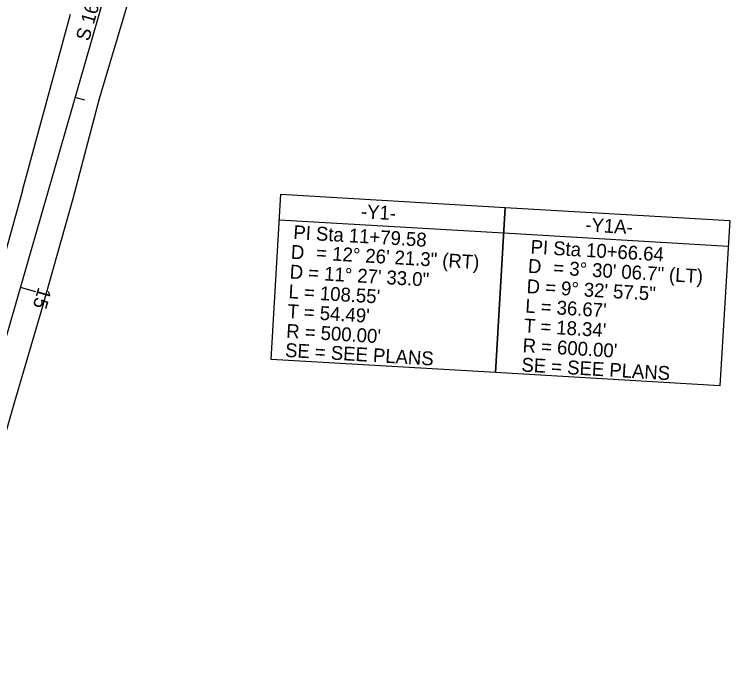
# Model space of a CAD drawing. Extents: x 2010838 to 2015151, y 441905 to 447792.
# Drawn here: x 2012294.2 to 2012655.8, y 444289.1 to 444614.7 of the extents above; entities that cross this region are included whole.
import ezdxf

# ---------------------------------------------------------------- set-up
doc = ezdxf.new("R2010")
doc.units = 0
for name, color, linetype in [('$AUDIT_BAD_LAYER1', 7, 'Continuous'), ('C-Building', 7, 'Continuous'), ('C-EOP 1', 7, 'Continuous'), ('CLRD', 7, 'Continuous'), ('Cont-2-Lidar', 7, 'Continuous'), ('Default_2FT_LIDAR_Contour', 7, 'Continuous'), ('Default_Parcels', 7, 'Continuous'), ('S-overhead electric', 7, 'Continuous')]:
    doc.layers.add(name, color=color, linetype=linetype)

msp = doc.modelspace()

# ---------------------------------------------------------------- linework, layer by layer
at = {"layer": '$AUDIT_BAD_LAYER1'}
msp.add_line((2012370.93, 444732.79), (2012193.35, 444115.92), dxfattribs=at)
at = {"layer": 'C-Building'}
msp.add_line((2012324.91, 444572.92), (2012329.71, 444571.54), dxfattribs=at)
at = {"layer": 'C-EOP 1'}
msp.add_line((2012297.24, 444476.83), (2012304.93, 444474.61), dxfattribs=at)
at = {"layer": 'CLRD'}
msp.add_line((2012370.93, 444732.79), (2012193.35, 444115.92), dxfattribs=at)
at = {"layer": 'Default_Parcels'}
for p, q in [((2012428.15, 444510.89), (2012541.6, 444504.21)), ((2012541.6, 444504.21), (2012655.05, 444497.52))]:
    msp.add_line(p, q, dxfattribs=at)
for points in [[(2012428.91, 444523.85), (2012542.37, 444517.16), (2012537.44, 444433.65), (2012423.99, 444440.34)], [(2012542.37, 444517.16), (2012655.82, 444510.48), (2012650.89, 444426.96), (2012537.44, 444433.65)]]:
    msp.add_lwpolyline(points, close=True, dxfattribs=at)
at = {"layer": 'S-overhead electric'}
msp.add_line((2012298.31, 444525.62), (2012322.65, 444614.7), dxfattribs=at)
for points in [[(2012214.85, 444140.57), (2012231.36, 444197.54), (2012246.95, 444252.5), (2012262.48, 444306.6), (2012277.82, 444361.05), (2012294.5, 444419.12), (2012308.07, 444465.48), (2012323.92, 444521.61), (2012337.25, 444572.21), (2012352.19, 444622.1), (2012368.35, 444674.41)], [(2012298.31, 444525.62), (2012284.21, 444475.17), (2012267.75, 444418.87), (2012251.33, 444361.5), (2012234.87, 444302.97), (2012222.75, 444260.78), (2012211.14, 444219.75), (2012193.27, 444158.36)]]:
    msp.add_lwpolyline(points, dxfattribs=at)
msp.add_ellipse((2012288.54, 444624.12), major_axis=(20.27, 29.02), ratio=0.999636, start_param=5.052702, end_param=5.052702, dxfattribs=at)

# ---------------------------------------------------------------- texts
at = {"layer": 'Cont-2-Lidar'}
msp.add_text('S 16%%d 03\' 35.1" W', height=7, rotation=73.9402, dxfattribs=at).set_placement((2012331.92, 444600.75))
at = {"layer": 'Default_2FT_LIDAR_Contour'}
msp.add_text('15', height=7, rotation=253.9402, dxfattribs=at).set_placement((2012306.41, 444477.11))
at = {"layer": 'Default_Parcels'}
for s, p in [('-Y1-', (2012469.28, 444511.69)), ('-Y1A-', (2012582.73, 444505)), ('PI Sta 11+79.58', (2012435.13, 444501.19)), ('D', (2012433.87, 444491.24)), ('PI Sta 10+66.64', (2012555.03, 444493.8)), ('= 12%%d 26\' 21.3" (RT)', (2012446.72, 444490.78)), ('D', (2012553.71, 444484.14)), ('D = 11%%d 27\' 33.0"', (2012433.28, 444481.26)), ('= 3%%d 30\' 06.7" (LT)', (2012566.53, 444483.25)), ('D = 9%%d 32\' 57.5"', (2012553.01, 444473.88)), ("L = 108.55'", (2012432.69, 444471.28)), ("L = 36.67'", (2012552.35, 444464.01)), ("T = 54.49'", (2012432.11, 444461.3)), ("R = 500.00'", (2012431.52, 444451.31)), ("T = 18.34'", (2012551.67, 444454.03)), ("R = 600.00'", (2012551, 444444.01)), ('SE = SEE PLANS', (2012430.95, 444441.65)), ('SE = SEE PLANS', (2012550.42, 444434.27))]:
    msp.add_text(s, height=7, rotation=356.6264, dxfattribs=at).set_placement(p)

doc.saveas('drawing.dxf')
